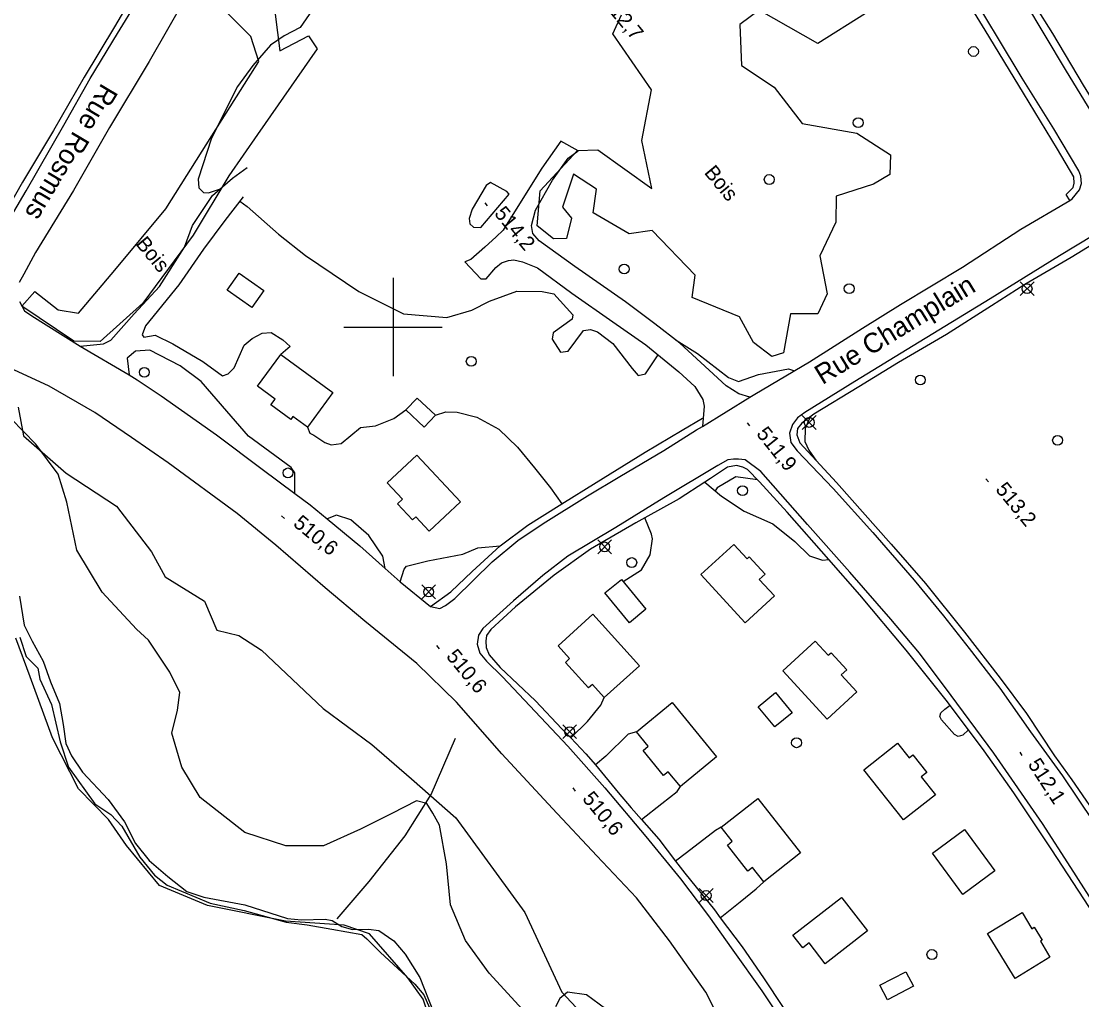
# Model space of a CAD drawing. Extents: x 347312 to 350503, y 6073086 to 6076432.
# Drawn here: x 348624.4 to 348840.1, y 6075263.3 to 6075462.2 of the extents above; entities that cross this region are included whole.
import ezdxf

# ---------------------------------------------------------------- set-up
doc = ezdxf.new("R2010")
doc.units = 0
for name, color, linetype in [('Level 1', 7, 'Continuous'), ('Level 19', 7, 'Continuous'), ('Level 2', 7, 'Continuous'), ('Level 21', 7, 'Continuous'), ('Level 22', 7, 'Continuous'), ('Level 3', 7, 'Continuous'), ('Level 31', 7, 'Continuous'), ('Level 36', 7, 'Continuous'), ('Level 4', 7, 'Continuous'), ('Level 44', 7, 'Continuous'), ('Level 61', 7, 'Continuous')]:
    doc.layers.add(name, color=color, linetype=linetype)

msp = doc.modelspace()

# ---------------------------------------------------------------- linework, layer by layer
at = {"layer": 'Level 1'}
for points in [[(348726.3, 6075261.31), (348719.57, 6075268.69), (348714.74, 6075275.31), (348711.69, 6075282.58), (348711.69, 6075282.58), (348710.87, 6075290.94), (348709.42, 6075298.78), (348708.11, 6075301.22), (348706.88, 6075303.16), (348704.8, 6075303.72), (348699.79, 6075301.14), (348693.41, 6075297.97), (348685.86, 6075294.61), (348678.18, 6075294.61), (348669.87, 6075297.28), (348660.81, 6075304.39), (348657.03, 6075310.57), (348655.05, 6075317.45), (348656.21, 6075322.14), (348656.68, 6075325.73), (348654.6, 6075329.85), (348650.27, 6075336.37), (348647.86, 6075338.64), (348640.86, 6075346.14), (348635.7, 6075354.64), (348633.69, 6075364.43), (348631.9, 6075370.13), (348627.38, 6075376.24), (348619.81, 6075383.95)], [(348743.18, 6075261.42), (348739.33, 6075264.33), (348735.5, 6075264.86), (348733.89, 6075263.52), (348733.03, 6075261.83)]]:
    msp.add_lwpolyline(points, dxfattribs=at)
at = {"layer": 'Level 19'}
for points in [[(348772.58, 6075385.79), (348770.33, 6075386.41), (348767.77, 6075388.04), (348764.32, 6075391.28), (348758.33, 6075396.76), (348753.26, 6075400.67), (348747.29, 6075405.12), (348736.94, 6075412.32), (348729.69, 6075417.5), (348728.43, 6075419.01), (348728.13, 6075420.64), (348728.99, 6075423.76), (348732.4, 6075429.89), (348735.61, 6075434.35), (348737.68, 6075435.84), (348734.12, 6075437.77), (348730.24, 6075432.3), (348723.71, 6075421.79), (348722.41, 6075419.73), (348720.96, 6075418.31), (348718.68, 6075416.26), (348715.81, 6075413.74), (348714.61, 6075413.27), (348717.83, 6075409.78), (348718.97, 6075409.8), (348720.91, 6075412.08), (348722.03, 6075413.08), (348723.51, 6075413.56), (348724.55, 6075413.67), (348726.32, 6075413.26), (348729.38, 6075412.04), (348736.35, 6075406.92), (348744.73, 6075401.1), (348751.42, 6075396.41), (348758.11, 6075390.91), (348761.37, 6075387.9), (348763.02, 6075385.28), (348763.26, 6075383.9), (348762.93, 6075379.82)], [(348636.37, 6075396.13), (348641.1, 6075396.6), (348642.61, 6075397.32), (348647.34, 6075402.67), (348652.55, 6075408.27), (348657.58, 6075416.26), (348659.26, 6075420.66), (348663.32, 6075426.73), (348667.39, 6075430.25), (348670.31, 6075432.44)], [(348669.5, 6075426.44), (348665.81, 6075421.66), (348661.45, 6075415.86), (348656.45, 6075408.57), (348649.67, 6075400.25), (348649, 6075398.42), (348649.33, 6075397.94), (348651.63, 6075398.34), (348655.25, 6075396.61), (348661.33, 6075393.01), (348665.34, 6075390.09), (348666.45, 6075390.48), (348667.67, 6075391.72), (348669.71, 6075396.34), (348671.35, 6075397.7), (348673.42, 6075398.74), (348675.2, 6075398.87), (348677.62, 6075397.41), (348679.1, 6075396.08), (348677.18, 6075394.43)], [(348680.05, 6075366.2), (348680.06, 6075370.35), (348679.3, 6075371.44), (348670.6, 6075377.84), (348666.22, 6075382.92), (348660.98, 6075388.95), (348656.75, 6075392.13), (348650.55, 6075395.34), (348647.65, 6075395.11), (348645.91, 6075393.67), (348646.36, 6075390.27)], [(348682.59, 6075379.68), (348683.07, 6075378.46), (348683.92, 6075378.07), (348686.16, 6075376.55), (348687.4, 6075376.07), (348689.48, 6075376.36), (348693.4, 6075379.61), (348696.47, 6075379.91), (348700.16, 6075381.45), (348702.62, 6075383.16)], [(348708.62, 6075382.07), (348710.74, 6075382.77), (348713.04, 6075382.72), (348717.06, 6075381.7), (348721.52, 6075379.23), (348725.3, 6075375.59), (348728.78, 6075371.41), (348732.03, 6075367.33), (348734.32, 6075364.05)], [(348763.41, 6075368.49), (348766.82, 6075365.67), (348771.39, 6075362.62), (348777.2, 6075359.99), (348781.68, 6075356.41), (348784.67, 6075353.54), (348787.3, 6075352.64), (348788.63, 6075352.77)], [(348698.43, 6075350.91), (348697.93, 6075353.43), (348695.07, 6075357.68), (348691.41, 6075360.81), (348688.54, 6075361.81), (348686.59, 6075361.05)], [(348746.8, 6075348.29), (348750.56, 6075350.66), (348752.32, 6075353.7), (348752.75, 6075356.98), (348752.55, 6075357.95), (348751.2, 6075361.22)], [(348701.43, 6075348.24), (348702.24, 6075350.79), (348702.71, 6075351.41), (348707.09, 6075352.48), (348714.22, 6075353.87), (348717.26, 6075355.11), (348721.81, 6075355.53)], [(348736.14, 6075316.5), (348739.54, 6075319.84), (348742.28, 6075323.17), (348742.95, 6075324.72)], [(348817.04, 6075318.13), (348815.85, 6075317.07), (348814.92, 6075316.79), (348814.15, 6075317.21), (348811.51, 6075320.17), (348811.16, 6075320.86), (348811.37, 6075321.64), (348812.24, 6075322.36), (348813.27, 6075323.17)], [(348749.48, 6075317.76), (348747.83, 6075317.29), (348743.25, 6075312.83), (348741.14, 6075311.01)], [(348750.52, 6075299.96), (348754.69, 6075303.19), (348757.8, 6075305.61), (348758.43, 6075306.66)], [(348766.76, 6075298.36), (348765.58, 6075297.69), (348759.69, 6075293.18), (348757.46, 6075291.49)], [(348766.55, 6075279.95), (348770.56, 6075283.19), (348773.81, 6075285.81), (348775.38, 6075287.28)]]:
    msp.add_lwpolyline(points, dxfattribs=at)
at = {"layer": 'Level 2'}
for points in [[(348718.72, 6075506.29), (348718.55, 6075505.87), (348712.32, 6075499.96), (348709.01, 6075498.34), (348705.59, 6075496.93), (348701.92, 6075494.19), (348699.25, 6075491.97), (348696.35, 6075487.77), (348688.71, 6075477.68), (348686.13, 6075471.65), (348684.8, 6075466.19), (348681.14, 6075460.91), (348677.9, 6075459.2)], [(348677.9, 6075459.2), (348675.09, 6075457.32), (348671.5, 6075453.14), (348668.35, 6075448.88), (348663.06, 6075438.41), (348660.39, 6075430.04), (348660.51, 6075428.27), (348661.45, 6075427.32), (348662.51, 6075427.3), (348664.89, 6075428.09)], [(348717.87, 6075420.27), (348723.59, 6075427.03), (348723.15, 6075427.57), (348719.83, 6075429.39), (348718.91, 6075428.78), (348716.12, 6075423.99), (348715.49, 6075422.05), (348715.64, 6075420.97), (348716.35, 6075420.29), (348717.87, 6075420.27)], [(348668.84, 6075425.59), (348670.35, 6075424.49), (348676.69, 6075418.86), (348682.21, 6075414.57), (348693.08, 6075407.21), (348702.12, 6075402.68), (348710.94, 6075401.94), (348716.01, 6075403.44), (348719.64, 6075405.24), (348725.17, 6075407.28), (348730.31, 6075407.25), (348732.69, 6075406.75), (348736.54, 6075402.49), (348736.45, 6075401.6), (348732.58, 6075398.83), (348732.37, 6075397.54), (348734.06, 6075394.88), (348735.6, 6075395.11), (348738.71, 6075399.33), (348740.13, 6075399.53), (348741.6, 6075399.03), (348744.68, 6075396.69), (348748.61, 6075391.61), (348749.88, 6075390.17), (348751.35, 6075390.49), (348753.9, 6075394.37)], [(348757.56, 6075397.35), (348761.9, 6075394.65), (348768.23, 6075389.75), (348770.26, 6075388.95), (348774.34, 6075390.37), (348780.42, 6075391.5), (348781.65, 6075391.14)], [(348784.83, 6075381.76), (348783.78, 6075379.4), (348783.74, 6075376.74), (348784.57, 6075375.02), (348785.99, 6075372.93)], [(348774.13, 6075368.93), (348769.69, 6075369.54), (348765.9, 6075367.3), (348765.52, 6075366.75)], [(348624.06, 6075345.35), (348624.97, 6075339.43), (348626.63, 6075336.14), (348628.88, 6075332.14), (348630.38, 6075327.92), (348632.16, 6075323.52), (348632.93, 6075319.22), (348633.44, 6075315.38), (348634.59, 6075312.87), (348636.83, 6075309.53), (348642.06, 6075304.01), (348645.42, 6075299.46), (348647.63, 6075295.03), (348650.44, 6075291.63)], [(348650.44, 6075291.63), (348654.21, 6075288.36), (348658.07, 6075285.3), (348661.52, 6075284.18), (348669.87, 6075282.59), (348678.54, 6075279.81), (348681.42, 6075279.54), (348686.22, 6075279.67), (348687.63, 6075279.38), (348689.6, 6075278.16), (348691.76, 6075277.61), (348695.03, 6075277.67), (348697.11, 6075277.4), (348700.18, 6075275.29), (348702.47, 6075272.53), (348705.44, 6075267.81), (348708.2, 6075260.78)]]:
    msp.add_lwpolyline(points, dxfattribs=at)
at = {"layer": 'Level 21'}
for points in [[(348620.39, 6075419.18), (348625.38, 6075427.67), (348633.04, 6075441.01), (348638.45, 6075450.53), (348643.95, 6075459.67), (348651.96, 6075472.77)], [(348839.48, 6075431.73), (348834.39, 6075440.28), (348827.93, 6075450.56), (348822.91, 6075458.94), (348815.03, 6075472.01)], [(348657.9, 6075467.03), (348650.44, 6075454), (348642.35, 6075440.54), (348635.04, 6075427.79), (348627.32, 6075415.16), (348624.93, 6075410.78), (348623.95, 6075409.07)], [(348901.69, 6075464.54), (348887.33, 6075455.72), (348875.86, 6075448.78), (348865.46, 6075442.27), (348856.18, 6075436.68), (348852.01, 6075434.36), (348850.3, 6075434.07), (348848.99, 6075434.19), (348847.94, 6075434.82), (348846.81, 6075435.99), (348841.45, 6075444.69), (348836.72, 6075452.34), (348828.46, 6075466.15)], [(348624.08, 6075405.19), (348625.06, 6075403.3), (348626.57, 6075402.3), (348636.37, 6075396.13), (348646.36, 6075390.27), (348647.99, 6075389.3), (348652.83, 6075386.02), (348664.11, 6075378.08), (348673.42, 6075371.13), (348680.05, 6075366.2), (348683.12, 6075363.91), (348686.59, 6075361.05), (348693.22, 6075355.57), (348698.43, 6075350.91), (348701.43, 6075348.24), (348707.59, 6075343.19), (348709.49, 6075342.81), (348710.66, 6075343.4), (348712.56, 6075344.82), (348720.13, 6075352.3), (348725.4, 6075356.66), (348730.54, 6075360.09), (348739.58, 6075365.7), (348746.12, 6075369.62), (348755.1, 6075374.95), (348761.74, 6075379.1), (348762.93, 6075379.82), (348772.58, 6075385.79), (348773.54, 6075386.38), (348784.72, 6075392.94), (348795.48, 6075399.75), (348803.18, 6075404.62), (348815.77, 6075412.2), (348827.68, 6075419.88), (348837.61, 6075425.75), (348838.13, 6075426.06), (348839.62, 6075427.89), (348839.98, 6075429.17), (348839.87, 6075430.65), (348839.48, 6075431.73)], [(348849.58, 6075422.98), (348835.5, 6075414.47), (348821.44, 6075405.76), (348805.74, 6075396.21), (348793.92, 6075388.97), (348783.74, 6075382.65), (348782.28, 6075381.59), (348781.25, 6075380.21), (348780.63, 6075378.42), (348780.91, 6075376.54), (348782.19, 6075374.82), (348789.51, 6075367.2), (348797.57, 6075358.24), (348805.98, 6075348.59), (348811.94, 6075341.35), (348817.17, 6075334.7), (348823.39, 6075326.6), (348829.61, 6075317.77), (348836.11, 6075308.78), (348842.38, 6075299.53)], [(348767.32, 6075257.49), (348763.59, 6075264.87), (348756.23, 6075275.26), (348749.54, 6075284.03), (348741.47, 6075292.55), (348732.44, 6075302.15), (348722.14, 6075313.27), (348712.94, 6075323.79), (348704.81, 6075331.65), (348694.28, 6075340.23), (348686.23, 6075347.02), (348676.16, 6075355.68), (348668.28, 6075362.09), (348654.25, 6075372.43), (348646.83, 6075377.55), (348639.36, 6075382.64), (348630.07, 6075388.02), (348616.69, 6075394.15)], [(348844.18, 6075280.23), (348837.85, 6075290.19), (348832.08, 6075299.11), (348822.16, 6075313.38), (348813.49, 6075325.16), (348807.08, 6075333.76), (348801.26, 6075340.67), (348792.88, 6075350.19), (348784.3, 6075359.86), (348774.77, 6075370.68), (348771.61, 6075373.03), (348770.27, 6075373.19), (348769.23, 6075373.16), (348768.07, 6075373.03), (348766.07, 6075371.9), (348755.08, 6075365.27), (348745.34, 6075359.24), (348735.54, 6075353.45), (348730.44, 6075349.52), (348724.48, 6075344.36), (348718.28, 6075338.77), (348717.4, 6075337.38), (348717.11, 6075335.55), (348717.64, 6075333.74), (348719.01, 6075332.09), (348722.26, 6075328.91), (348727.85, 6075323), (348735.54, 6075314.85), (348743.07, 6075306.34), (348751.43, 6075296.47), (348758.45, 6075287.84), (348764.15, 6075280.36), (348769.11, 6075273.4), (348775.02, 6075265.12), (348782.65, 6075253.59)]]:
    msp.add_lwpolyline(points, dxfattribs=at)
at = {"layer": 'Level 22'}
for points in [[(348837.61, 6075425.75), (348836.85, 6075426.95), (348838.29, 6075428.37), (348838.53, 6075429.25), (348838.45, 6075430.53), (348835.14, 6075436.13), (348828.18, 6075447.56), (348820.39, 6075460.34), (348812.99, 6075472.38), (348805.23, 6075485.39), (348799.62, 6075494.11), (348792.63, 6075506.03), (348786.31, 6075516.42), (348780.25, 6075526.49), (348773.72, 6075536.76), (348766.95, 6075547.96), (348764.72, 6075551), (348763.64, 6075551.84), (348762.61, 6075552.18), (348761.64, 6075552.35), (348760.24, 6075551.94), (348756.72, 6075549.93), (348749.31, 6075544.99), (348744.96, 6075541.98)], [(348901.69, 6075464.54), (348900.87, 6075465.84), (348895.33, 6075462.45), (348884.32, 6075455.81), (348874.88, 6075449.87), (348864.55, 6075443.73), (348853.03, 6075436.67), (348850.81, 6075435.72), (348850.11, 6075435.75), (348849.01, 6075436.26), (348848.15, 6075437.2), (348847.06, 6075438.41), (348840.37, 6075449.16), (348834.18, 6075459.65), (348826.97, 6075471.1), (348820.1, 6075482.15), (348819.03, 6075481.41)], [(348650.14, 6075472.57), (348643.39, 6075461.04), (348637.21, 6075450.82), (348630.93, 6075439.98), (348624.69, 6075429.47), (348620.41, 6075421.94)], [(348846.99, 6075419.72), (348837.89, 6075414.14), (348828.45, 6075408.65), (348821.72, 6075404.35), (348812.53, 6075398.47), (348802.79, 6075392.8), (348794.71, 6075387.84), (348785.6, 6075382.32), (348783.12, 6075380.5), (348782.24, 6075379.39), (348782.08, 6075378.13), (348782.71, 6075376.47), (348790.16, 6075368.43), (348801.3, 6075355.86), (348808.26, 6075347.87), (348816.19, 6075337.97), (348823.44, 6075328.63), (348828.79, 6075321.48), (348834.51, 6075312.9), (348838, 6075307.97), (348844.48, 6075298.66)], [(348707.59, 6075343.19), (348711.76, 6075346.2), (348716.1, 6075350.35), (348721.81, 6075355.53), (348727.43, 6075359.74), (348733.77, 6075363.71), (348734.32, 6075364.05), (348741.33, 6075368.39), (348751.25, 6075374.58), (348758.79, 6075379.02), (348762.93, 6075381.47)], [(348842.61, 6075280.47), (348833.95, 6075293.77), (348826.21, 6075305.33), (348820.21, 6075313.9), (348812.77, 6075323.84), (348804.35, 6075334.31), (348794.9, 6075345.58), (348788.63, 6075352.77), (348780.15, 6075362.39), (348774.51, 6075368.54), (348772.11, 6075371.06), (348771.16, 6075371.56), (348769.87, 6075371.84), (348768.03, 6075371.52), (348764.53, 6075369.21), (348763.41, 6075368.49), (348758.17, 6075365.08), (348751.2, 6075361.22), (348749.4, 6075360.22), (348740.18, 6075354.84), (348732.77, 6075349.61), (348724.88, 6075343.15), (348719.88, 6075338.56), (348719.03, 6075337.32), (348718.84, 6075336.19), (348718.96, 6075334.86), (348719.57, 6075333.41), (348721.8, 6075330.82), (348728.96, 6075324.03), (348734.32, 6075318.39), (348736.14, 6075316.5), (348739.24, 6075313.29), (348741.14, 6075311.01), (348745.77, 6075305.45), (348748.44, 6075302.32), (348750.52, 6075299.96), (348754.03, 6075295.96), (348757.46, 6075291.49), (348759.33, 6075289.05), (348765.35, 6075281.54), (348766.55, 6075279.95), (348770.99, 6075274.03), (348775.32, 6075267.74), (348779.33, 6075261.73)], [(348688.63, 6075279.73), (348695.12, 6075287.36), (348702.5, 6075296.64), (348707.73, 6075305.04), (348712.7, 6075316.46)]]:
    msp.add_lwpolyline(points, dxfattribs=at)
at = {"layer": 'Level 3'}
for p, q in [((348718.64, 6075425.25), (348719.15, 6075424.63)), ((348771.98, 6075380.54), (348772.48, 6075379.92)), ((348820.56, 6075369.18), (348821.07, 6075368.56)), ((348677.32, 6075361.62), (348677.94, 6075361.11)), ((348708.86, 6075335.26), (348709.37, 6075334.64)), ((348827.45, 6075313.6), (348827.88, 6075312.93)), ((348736.54, 6075306.34), (348737.05, 6075305.72))]:
    msp.add_line(p, q, dxfattribs=at)
at = {"layer": 'Level 31'}
for points in [[(348666.26, 6075407.53), (348668.71, 6075410.98), (348673.74, 6075407.42), (348671.28, 6075403.96), (348666.26, 6075407.53)], [(348677.18, 6075394.43), (348687.73, 6075386.71), (348682.59, 6075379.68), (348679.64, 6075381.84), (348679.19, 6075381.22), (348675.15, 6075384.18), (348676.01, 6075385.36), (348672.45, 6075387.97), (348677.18, 6075394.43)], [(348704.88, 6075385.57), (348708.62, 6075382.07), (348706.36, 6075379.66), (348702.62, 6075383.16), (348704.88, 6075385.57)], [(348704.85, 6075373.99), (348713.73, 6075364.49), (348707.35, 6075358.53), (348704.61, 6075361.46), (348703.93, 6075360.83), (348700.91, 6075364.07), (348701.9, 6075365), (348698.79, 6075368.33), (348704.85, 6075373.99)], [(348771.6, 6075339.92), (348762.62, 6075349.71), (348769.3, 6075355.83), (348771.98, 6075352.9), (348772.45, 6075353.33), (348775.67, 6075349.81), (348774.48, 6075348.73), (348777.55, 6075345.38), (348771.6, 6075339.92)], [(348746.45, 6075348.72), (348751.43, 6075342.65), (348748.07, 6075339.9), (348743.09, 6075345.97), (348746.45, 6075348.72)], [(348740.64, 6075341.64), (348750.1, 6075331.18), (348742.95, 6075324.72), (348740.54, 6075327.38), (348739.74, 6075326.66), (348735.06, 6075331.84), (348735.92, 6075332.62), (348733.55, 6075335.23), (348740.64, 6075341.64)], [(348788.28, 6075320.32), (348779.27, 6075330.16), (348785.86, 6075336.2), (348788.5, 6075333.32), (348789.06, 6075333.82), (348792.25, 6075330.34), (348791.14, 6075329.33), (348794.33, 6075325.86), (348788.28, 6075320.32)], [(348777.63, 6075318.74), (348774.28, 6075322.86), (348777.78, 6075325.71), (348781.13, 6075321.59), (348777.63, 6075318.74)], [(348756.73, 6075323.7), (348765.77, 6075312.66), (348758.43, 6075306.66), (348755.98, 6075309.65), (348755.02, 6075308.87), (348750.85, 6075313.97), (348751.89, 6075314.81), (348749.48, 6075317.76), (348756.73, 6075323.7)], [(348803.82, 6075299.84), (348795.74, 6075310.01), (348802.61, 6075315.47), (348804.98, 6075312.49), (348805.72, 6075313.08), (348808.56, 6075309.51), (348807.4, 6075308.59), (348810.28, 6075304.97), (348803.82, 6075299.84)], [(348774.17, 6075304.18), (348782.84, 6075293.13), (348775.38, 6075287.28), (348773.11, 6075290.18), (348772.17, 6075289.43), (348768.01, 6075294.74), (348768.99, 6075295.51), (348766.76, 6075298.36), (348774.17, 6075304.18)], [(348816.18, 6075297.88), (348822.34, 6075289.48), (348815.85, 6075284.72), (348809.69, 6075293.12), (348816.18, 6075297.88)], [(348791.24, 6075284.04), (348796.48, 6075277.28), (348787.9, 6075270.62), (348784.59, 6075274.88), (348783.31, 6075273.88), (348781.32, 6075276.43), (348791.19, 6075284.09), (348791.24, 6075284.04)], [(348826.48, 6075267.64), (348820.91, 6075276.76), (348827.9, 6075281.01), (348829.89, 6075277.74), (348830.38, 6075278.03), (348831.99, 6075275.39), (348831.63, 6075275.18), (348833.58, 6075271.97), (348826.48, 6075267.64)], [(348800.52, 6075263.3), (348798.99, 6075266.23), (348804.27, 6075269), (348805.81, 6075266.07), (348800.52, 6075263.3)]]:
    msp.add_lwpolyline(points, dxfattribs=at)
at = {"layer": 'Level 36'}
for p, q in [((348827.53, 6075406.39), (348830.35, 6075409.21)), ((348827.53, 6075409.21), (348830.35, 6075406.39)), ((348783.22, 6075379.21), (348786.04, 6075382.03)), ((348783.22, 6075382.03), (348786.04, 6075379.21)), ((348741.62, 6075353.92), (348744.44, 6075356.74)), ((348741.62, 6075356.74), (348744.44, 6075353.92)), ((348705.83, 6075344.77), (348708.65, 6075347.59)), ((348705.83, 6075347.59), (348708.65, 6075344.77)), ((348734.51, 6075316.36), (348737.33, 6075319.18)), ((348734.51, 6075319.18), (348737.33, 6075316.36)), ((348762.27, 6075283.07), (348765.09, 6075285.89)), ((348762.27, 6075285.89), (348765.09, 6075283.07))]:
    msp.add_line(p, q, dxfattribs=at)
for centre in [(348818.04, 6075456.01), (348794.59, 6075441.53), (348776.5, 6075429.99), (348747, 6075411.8), (348792.76, 6075407.81), (348828.94, 6075407.8), (348715.9, 6075393.04), (348649.43, 6075390.81), (348807.23, 6075389.26), (348784.63, 6075380.62), (348835.13, 6075377), (348678.63, 6075370.37), (348771.07, 6075366.76), (348743.03, 6075355.33), (348748.55, 6075352.15), (348707.24, 6075346.18), (348735.92, 6075317.77), (348782.05, 6075315.52), (348763.68, 6075284.48), (348809.57, 6075272.49)]:
    msp.add_circle(centre, 1, dxfattribs=at)
at = {"layer": 'Level 4'}
msp.add_lwpolyline([(348624.1, 6075337.01), (348625.42, 6075333.06), (348627.79, 6075330.66), (348628.21, 6075328.44), (348630.53, 6075323.28), (348632.3, 6075315.7), (348634.01, 6075310.56), (348639.34, 6075303.14), (348642.6, 6075300.94), (348644.86, 6075298.59), (348648.52, 6075292.28), (348651.48, 6075288.62), (348654.09, 6075286.56), (348662.84, 6075282.95), (348669.75, 6075281.44), (348678.28, 6075279.08), (348682.52, 6075278.52), (348687.56, 6075277.64), (348693.66, 6075276.57), (348694.69, 6075275.69), (348697.44, 6075272.92), (348704.44, 6075266.5), (348706.3, 6075264.27), (348709.06, 6075257.95)], dxfattribs=at)
at = {"layer": 'Level 44'}
for points in [[(348659.33, 6075418.68), (348649.16, 6075404.85), (348640.46, 6075397.04), (348635.12, 6075397.12), (348624.52, 6075404.26), (348627.18, 6075407.21), (348631.93, 6075403.49), (348636.07, 6075402.86), (348643.46, 6075411.54), (348653.83, 6075424.04), (348663.18, 6075438.85), (348672.73, 6075453.96), (348671.06, 6075459.03), (348660.47, 6075469.76)], [(348796.08, 6075463.71), (348786.39, 6075457.63), (348774.44, 6075464.39), (348770.55, 6075461.47), (348770.84, 6075453.16), (348777.51, 6075448.77), (348783.23, 6075441.36), (348794.32, 6075439.43), (348801.15, 6075435.03), (348801.03, 6075431.02), (348797.72, 6075429.03), (348790.09, 6075426.62), (348790.01, 6075421.3), (348786.82, 6075414.46), (348788.25, 6075406.78), (348786.39, 6075402.68), (348780.8, 6075402.71), (348779.41, 6075394.8), (348777.03, 6075394.03), (348773.33, 6075396.84)], [(348676.01, 6075463.58), (348676.96, 6075456.11), (348682.83, 6075459.18), (348684.56, 6075456.56), (348672.43, 6075439.16), (348666.64, 6075430.76), (348659.33, 6075418.68)], [(348773.33, 6075396.84), (348770.45, 6075402.11), (348760.86, 6075406.03), (348761.45, 6075410.57), (348752.68, 6075419.66), (348748.01, 6075418.95), (348740.68, 6075423.23), (348741.37, 6075428), (348736.72, 6075431.06), (348734.46, 6075424.38), (348736.31, 6075422.16), (348735.26, 6075417.99), (348732.62, 6075417.91), (348729.34, 6075420.59), (348729.92, 6075427.67), (348737.5, 6075435.9), (348741.62, 6075436.02), (348752.65, 6075428.19), (348750.59, 6075437.89), (348752.53, 6075448.21), (348744.72, 6075459.58), (348746.47, 6075463.44)], [(348623.79, 6075383.72), (348624.89, 6075377.87), (348633.56, 6075370.32), (348643.8, 6075363.63), (348650.92, 6075354.34), (348653.65, 6075349.24), (348661.67, 6075344.31), (348664.16, 6075338.41), (348668.67, 6075337.33), (348673.25, 6075334.36), (348685.82, 6075322.51), (348695.67, 6075315.18), (348703.75, 6075308.18), (348712.74, 6075300.28), (348726.77, 6075281.04), (348734.33, 6075264.87), (348744, 6075254.51)], [(348709.49, 6075253.23), (348706.14, 6075263.43), (348703, 6075267.76), (348695.25, 6075276.72), (348690.05, 6075278.44), (348678.17, 6075279.3), (348662.29, 6075282.42), (348652.53, 6075286.54), (348645.78, 6075294.66), (348642.15, 6075299.94), (348636.06, 6075306.19), (348630.76, 6075316.56), (348626.22, 6075328.91), (348623.33, 6075336.75)]]:
    msp.add_lwpolyline(points, dxfattribs=at)
at = {"layer": 'Level 61'}
for p, q in [((348700, 6075410), (348700, 6075390)), ((348690, 6075400), (348710, 6075400))]:
    msp.add_line(p, q, dxfattribs=at)

# ---------------------------------------------------------------- texts
at = {"layer": 'Level 21'}
for s, rotation, p in [('Rue Rosmus', 239.3006, (348640.81, 6075449.76)), ('Rue Champlain', 31.4079, (348787.32, 6075388.2))]:
    msp.add_text(s, height=4, rotation=rotation, dxfattribs=at).set_placement(p)
at = {"layer": 'Level 3'}
for s, rotation, p in [('512,7', 309.5679, (348742.48, 6075465.77)), ('514,2', 309.5679, (348720.45, 6075423.01)), ('511,9', 308.6937, (348773.75, 6075378.27)), ('513,2', 309.5679, (348822.37, 6075366.94)), ('510,6', 320.4332, (348679.52, 6075359.76)), ('510,6', 309.5679, (348710.67, 6075333.02)), ('512,1', 303.0143, (348828.99, 6075311.16)), ('510,6', 309.5888, (348738.35, 6075304.1))]:
    msp.add_text(s, height=3, rotation=rotation, dxfattribs=at).set_placement(p)
at = {"layer": 'Level 44'}
for p in [(348763.14, 6075431.34), (348647.54, 6075416.87)]:
    msp.add_text('Bois', height=3, rotation=309.568, dxfattribs=at).set_placement(p)

doc.saveas('drawing.dxf')
